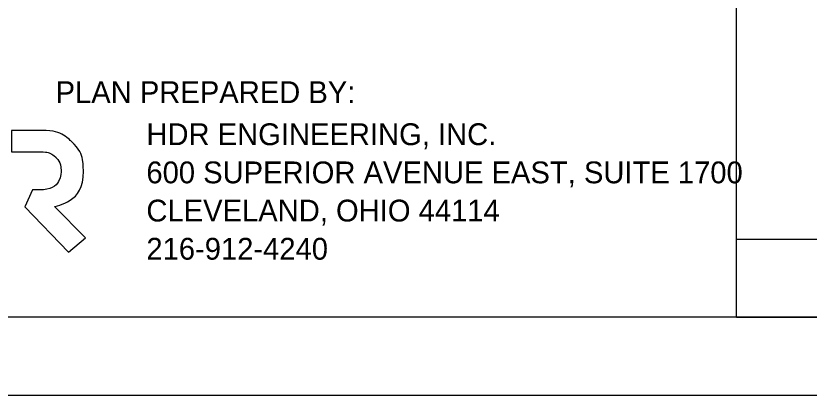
# Model space of a CAD drawing. Extents: x 0 to 34, y 0 to 22.
# Drawn here: x 2.62 to 7.72, y 0 to 2.43 of the extents above; entities that cross this region are included whole.
import ezdxf

# ---------------------------------------------------------------- set-up
doc = ezdxf.new("R2010")
doc.units = 0
for name, color, linetype in [('SH_Border', 7, 'Continuous'), ('SH_Cut_Line', 7, 'Continuous'), ('SH_Data', 7, 'Continuous'), ('SH_Text', 7, 'Continuous')]:
    doc.layers.add(name, color=color, linetype=linetype)

msp = doc.modelspace()

# ---------------------------------------------------------------- linework, layer by layer
at = {"layer": 'SH_Border'}
msp.add_lwpolyline([(1.5, 21.5), (33.5, 21.5), (33.5, 0.5), (1.5, 0.5)], close=True, dxfattribs=at)
at = {"layer": 'SH_Cut_Line'}
msp.add_lwpolyline([(0, 0), (34, 0), (34, 22), (0, 22)], close=True, dxfattribs=at)
at = {"layer": 'SH_Data'}
for q in [(7.2509, 3.75), (10.0509, 0.5)]:
    msp.add_line((7.2509, 0.5), q, dxfattribs=at)
for points in [[(2.7573, 1.6987), (2.5963, 1.6987), (2.5963, 1.5619), (2.768, 1.5619)], [(2.7749, 1.3172), (2.7321, 1.3172), (2.6817, 1.2086), (2.9626, 0.9174), (3.0719, 1.0091), (2.8728, 1.21)]]:
    msp.add_lwpolyline(points, dxfattribs=at)
msp.add_lwpolyline([(7.2509, 0.5), (7.2509, 1), (10.0509, 1), (10.0509, 0.5)], close=True, dxfattribs=at)
for points in [[(2.9788, 1.6303), (2.9788, 1.6303), (2.9202, 1.6854), (2.8552, 1.6987), (2.7573, 1.6987)], [(3.0578, 1.4368), (3.0578, 1.4368), (3.0578, 1.5161), (3.0352, 1.5772), (2.9788, 1.6303)], [(2.768, 1.5619), (2.768, 1.5619), (2.8197, 1.5619), (2.8548, 1.5511), (2.8801, 1.5262)], [(2.8801, 1.5262), (2.8801, 1.5262), (2.9031, 1.5035), (2.9151, 1.4736), (2.9151, 1.4398)], [(2.9151, 1.4398), (2.9151, 1.4398), (2.9151, 1.363), (2.8488, 1.3172), (2.7749, 1.3172)], [(2.8728, 1.21), (2.8728, 1.21), (2.9828, 1.2305), (3.0578, 1.331), (3.0578, 1.4368)]]:
    msp.add_open_spline(points, degree=3, dxfattribs=at)

# ---------------------------------------------------------------- texts
for s, p in [('HDR ENGINEERING, INC.', (3.4625, 1.6042)), ('600 SUPERIOR AVENUE EAST, SUITE 1700', (3.4625, 1.3592)), ('CLEVELAND, OHIO 44114', (3.4625, 1.1142)), ('216-912-4240', (3.4625, 0.8692))]:
    msp.add_text(s, height=0.14, dxfattribs=at).set_placement(p)
at = {"layer": 'SH_Text'}
msp.add_text('PLAN PREPARED BY:', height=0.14, dxfattribs=at).set_placement((2.8795, 1.8741))

doc.saveas('drawing.dxf')
